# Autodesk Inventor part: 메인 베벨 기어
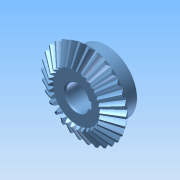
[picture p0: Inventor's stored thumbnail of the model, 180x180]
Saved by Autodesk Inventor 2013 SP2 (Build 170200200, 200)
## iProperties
Created: 2026-07
Part Number: 메인 베벨 기어
Material: Generic
Document SubType Name: Modeling
Designer: aa
Density: 1 g/cm^3
변환 표준: STEP AP214IS
전처리기: Build: 200, Release: 2013 SP2 Update 6 - Date: Thu 07/17/2014
전송 단위: 밀리미터
불확실성: 0.01
Author: aa
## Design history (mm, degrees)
node "메인 베벨기어1"
body "Solid1"
node "기준1"
